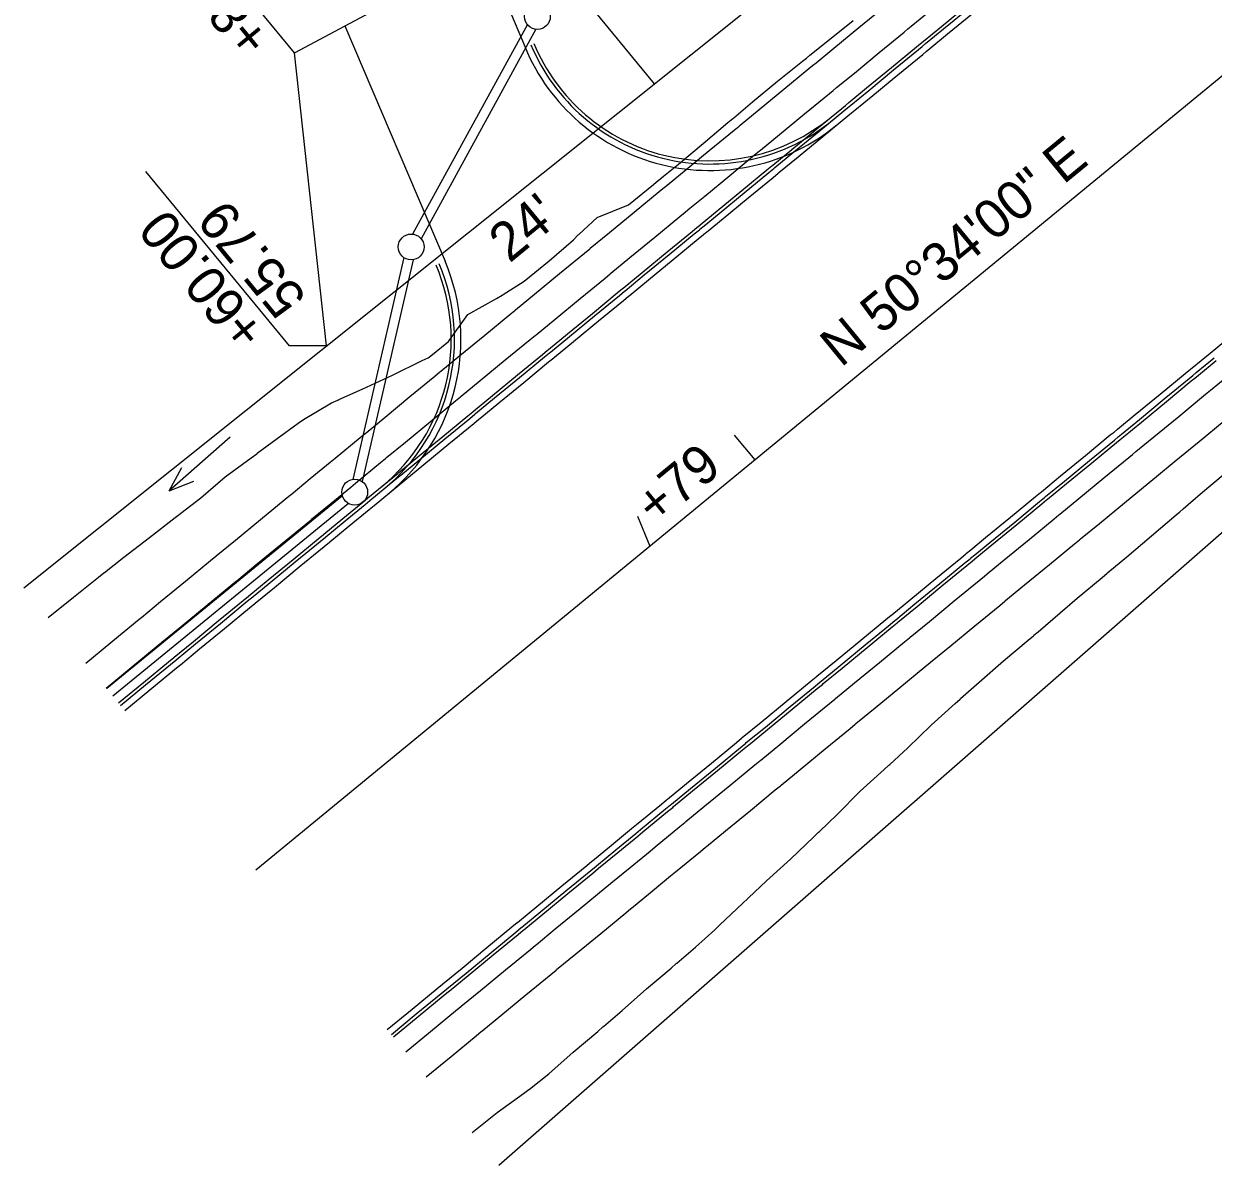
# Model space of a CAD drawing. Extents: x 1147550 to 1149124, y 2017436 to 2018779.
# Drawn here: x 1147550.1 to 1147734.3, y 2017436.4 to 2017613.3 of the extents above; entities that cross this region are included whole.
import ezdxf

# ---------------------------------------------------------------- set-up
doc = ezdxf.new("R2010")
doc.units = 0
for name, color, linetype in [('S_EDGE_CONCRETE', 7, 'Continuous'), ('S_ELECTRIC_UTILITIES', 7, 'Continuous'), ('S_HEADWALL', 7, 'Continuous'), ('S_MAILBOX', 7, 'Continuous'), ('S_RDW_PT_SYM', 7, 'Continuous'), ('S_SECONDARY_CTL', 7, 'Continuous'), ('S_TANK', 7, 'Continuous'), ('S_TELEPHONE_UTILITIES', 7, 'Continuous'), ('S_TELEPHONE_UTILITIES_ANNOT', 7, 'Continuous')]:
    doc.layers.add(name, color=color, linetype=linetype)

msp = doc.modelspace()

# ---------------------------------------------------------------- linework, layer by layer
at = {"layer": 'S_EDGE_CONCRETE'}
msp.add_line((1147586.06, 2017482.16), (1147825.51, 2017679.08), dxfattribs=at)
msp.add_lwpolyline([(1147660.13, 2017549.54), (1147663.3, 2017545.68)], dxfattribs=at)
at = {"layer": 'S_ELECTRIC_UTILITIES'}
for points in [[(1147592.01, 2017608.75), (1147569.78, 2017635.79)], [(1147596.97, 2017563.36), (1147591.24, 2017563.36), (1147569.01, 2017590.39)]]:
    msp.add_lwpolyline(points, dxfattribs=at)
at = {"layer": 'S_HEADWALL'}
for p, q in [((1147621.53, 2017624.53), (1147627.73, 2017609.62)), ((1147599.83, 2017612.94), (1147615.34, 2017576.47)), ((1147645.14, 2017536.95), (1147647.08, 2017532.34))]:
    msp.add_line(p, q, dxfattribs=at)
for centre, radius, start, end in [((1147656.35, 2017621.53), 31, 202.599, 309.4333), ((1147656.35, 2017621.53), 30, 202.599, 309.4333), ((1147656.35, 2017621.53), 29.5, 202.599, 309.4333), ((1147586.81, 2017564.34), 30, 309.4333, 23.0331), ((1147586.81, 2017564.34), 31, 309.4333, 23.0331), ((1147586.81, 2017564.34), 29.5, 309.4333, 23.0331)]:
    msp.add_arc(centre, radius, start, end, dxfattribs=at)
at = {"layer": 'S_MAILBOX'}
msp.add_line((1147627.98, 2017627.98), (1147647.75, 2017603.95), dxfattribs=at)
for points in [[(1147550.1, 2017525.89), (1147894.72, 2017801.4), (1147903.55, 2017831.14), (1148035.64, 2017933.4), (1148261.5, 2018084.85), (1148285.74, 2018084.65), (1148479.1, 2018223.18), (1148835.76, 2018573.62)], [(1147623.68, 2017436.42), (1147751.67, 2017548.43), (1147958.55, 2017704.02), (1148020.45, 2017753.36), (1148124.6, 2017828.73), (1148174.25, 2017853.51), (1148282.74, 2017941.53), (1148421.63, 2018031.39), (1148612.18, 2018197.22), (1148639.91, 2018214.06), (1148753.45, 2018306.48), (1148799.03, 2018350.69)], [(1147596.97, 2017563.36), (1147592.01, 2017608.75), (1147627.98, 2017627.98)]]:
    msp.add_lwpolyline(points, dxfattribs=at)
at = {"layer": 'S_SECONDARY_CTL'}
for points in [[(1147553.88, 2017521.3), (1147557.78, 2017524.42), (1147561.69, 2017527.55), (1147562.51, 2017528.21), (1147562.59, 2017528.27), (1147565.62, 2017530.64), (1147569.58, 2017533.69), (1147573.54, 2017536.75), (1147574.38, 2017537.39), (1147574.45, 2017537.45), (1147577.5, 2017539.8), (1147581.3, 2017543.06), (1147585.33, 2017546.03), (1147586.19, 2017546.65), (1147586.26, 2017546.71), (1147589.37, 2017548.99), (1147592.6, 2017551.36), (1147593.41, 2017551.95), (1147597.76, 2017554.52), (1147598.72, 2017554.95), (1147598.9, 2017555.03), (1147602.49, 2017556.65), (1147607.19, 2017558.8), (1147611.81, 2017561.07), (1147612.75, 2017561.52), (1147612.9, 2017561.59), (1147615.86, 2017564.01), (1147618.88, 2017568.2), (1147623.3, 2017570.71), (1147624.2, 2017571.22), (1147624.34, 2017571.3), (1147627.59, 2017573.36), (1147631.47, 2017576.51), (1147635.23, 2017579.81), (1147635.98, 2017580.54), (1147636.06, 2017580.62), (1147638.9, 2017583.22), (1147643.75, 2017585.19), (1147647.61, 2017588.37), (1147648.42, 2017589.03), (1147648.51, 2017589.1), (1147649.17, 2017589.63), (1147651.51, 2017591.51), (1147655.34, 2017594.72), (1147659.16, 2017597.95), (1147659.92, 2017598.59), (1147660.07, 2017598.71), (1147662.98, 2017601.17), (1147666.83, 2017604.36), (1147670.73, 2017607.49), (1147671.31, 2017607.95), (1147671.85, 2017608.38), (1147674.64, 2017610.61), (1147678.54, 2017613.74)], [(1147619.52, 2017441.48), (1147623.43, 2017444.6), (1147627.49, 2017447.54), (1147628.34, 2017448.16), (1147628.42, 2017448.21), (1147631.44, 2017450.6), (1147635.19, 2017453.92), (1147638.99, 2017457.16), (1147639.8, 2017457.85), (1147639.87, 2017457.9), (1147642.8, 2017460.41), (1147646.54, 2017463.73), (1147650.35, 2017466.97), (1147651.15, 2017467.65), (1147651.22, 2017467.71), (1147654.15, 2017470.22), (1147657.11, 2017472.91), (1147657.85, 2017473.59), (1147661.49, 2017477.04), (1147662.22, 2017477.73), (1147662.36, 2017477.86), (1147665.14, 2017480.47), (1147668.83, 2017483.85), (1147672.46, 2017487.31), (1147673.2, 2017488.01), (1147673.32, 2017488.12), (1147676.08, 2017490.78), (1147679.62, 2017494.35), (1147683.33, 2017497.71), (1147684.09, 2017498.39), (1147684.21, 2017498.5), (1147687.01, 2017501.11), (1147690.61, 2017504.6), (1147694.33, 2017507.94), (1147695.11, 2017508.64), (1147695.19, 2017508.72), (1147698.06, 2017511.28), (1147701.84, 2017514.56), (1147705.66, 2017517.79), (1147706.46, 2017518.46), (1147706.54, 2017518.53), (1147707.19, 2017519.08), (1147709.47, 2017521.03), (1147713.26, 2017524.28), (1147717.1, 2017527.49), (1147717.87, 2017528.13), (1147718.01, 2017528.25), (1147720.93, 2017530.7), (1147724.75, 2017533.94), (1147728.56, 2017537.18), (1147729.12, 2017537.65), (1147729.64, 2017538.1), (1147732.37, 2017540.41), (1147736.17, 2017543.66)]]:
    msp.add_lwpolyline(points, dxfattribs=at)
at = {"layer": 'S_TANK'}
for p, q in [((1147582.05, 2017549.22), (1147572.61, 2017540.92)), ((1147572.61, 2017540.92), (1147574.57, 2017544.51)), ((1147572.61, 2017540.92), (1147576.42, 2017542.41))]:
    msp.add_line(p, q, dxfattribs=at)
at = {"layer": 'S_TELEPHONE_UTILITIES'}
for points in [[(1147559.7, 2017514.22), (1147563.57, 2017517.39), (1147567.43, 2017520.57), (1147568.24, 2017521.24), (1147568.32, 2017521.3), (1147571.29, 2017523.74), (1147575.15, 2017526.92), (1147579.01, 2017530.09), (1147579.83, 2017530.77), (1147579.9, 2017530.82), (1147582.88, 2017533.27), (1147586.74, 2017536.45), (1147590.6, 2017539.62), (1147591.42, 2017540.29), (1147591.49, 2017540.35), (1147594.46, 2017542.8), (1147597.55, 2017545.34), (1147598.32, 2017545.97), (1147602.18, 2017549.15), (1147602.96, 2017549.79), (1147603.11, 2017549.91), (1147606.05, 2017552.33), (1147609.91, 2017555.5), (1147613.77, 2017558.68), (1147614.56, 2017559.32), (1147614.68, 2017559.43), (1147617.63, 2017561.85), (1147621.49, 2017565.03), (1147625.36, 2017568.21), (1147626.14, 2017568.85), (1147626.27, 2017568.96), (1147629.22, 2017571.38), (1147633.08, 2017574.56), (1147636.94, 2017577.73), (1147637.75, 2017578.4), (1147637.83, 2017578.47), (1147640.8, 2017580.91), (1147644.66, 2017584.08), (1147648.53, 2017587.26), (1147649.33, 2017587.92), (1147649.42, 2017587.99), (1147650.07, 2017588.53), (1147652.39, 2017590.44), (1147656.25, 2017593.61), (1147660.11, 2017596.79), (1147660.88, 2017597.42), (1147661.03, 2017597.54), (1147663.97, 2017599.96), (1147667.84, 2017603.14), (1147671.7, 2017606.32), (1147672.26, 2017606.78), (1147672.8, 2017607.22), (1147675.56, 2017609.49), (1147679.42, 2017612.67), (1147683.28, 2017615.84)], [(1147562.88, 2017510.35), (1147566.74, 2017513.53), (1147570.6, 2017516.71), (1147571.42, 2017517.38), (1147571.49, 2017517.44), (1147574.47, 2017519.88), (1147578.33, 2017523.06), (1147582.19, 2017526.23), (1147583.01, 2017526.9), (1147583.08, 2017526.96), (1147586.05, 2017529.41), (1147589.91, 2017532.58), (1147593.78, 2017535.76), (1147594.59, 2017536.43), (1147594.66, 2017536.49), (1147597.64, 2017538.94), (1147600.73, 2017541.48), (1147601.5, 2017542.11), (1147605.36, 2017545.29), (1147606.14, 2017545.93), (1147606.28, 2017546.05), (1147609.22, 2017548.46), (1147613.08, 2017551.64), (1147616.95, 2017554.82), (1147617.73, 2017555.46), (1147617.86, 2017555.57), (1147620.81, 2017557.99), (1147624.67, 2017561.17), (1147628.53, 2017564.34), (1147629.32, 2017564.99), (1147629.44, 2017565.09), (1147632.39, 2017567.52), (1147636.26, 2017570.7), (1147640.12, 2017573.87), (1147640.92, 2017574.53), (1147641.01, 2017574.6), (1147643.98, 2017577.05), (1147647.84, 2017580.22), (1147651.7, 2017583.4), (1147652.51, 2017584.06), (1147652.59, 2017584.13), (1147653.25, 2017584.67), (1147655.56, 2017586.57), (1147659.43, 2017589.75), (1147663.29, 2017592.93), (1147664.06, 2017593.56), (1147664.21, 2017593.68), (1147667.15, 2017596.1), (1147671.01, 2017599.28), (1147674.87, 2017602.45), (1147675.44, 2017602.92), (1147675.97, 2017603.36), (1147678.74, 2017605.63), (1147682.6, 2017608.81), (1147686.46, 2017611.98), (1147687.02, 2017612.45), (1147687.56, 2017612.88), (1147690.32, 2017615.16)], [(1147564.79, 2017508.04), (1147568.65, 2017511.21), (1147572.51, 2017514.39), (1147573.33, 2017515.06), (1147573.4, 2017515.12), (1147576.37, 2017517.56), (1147580.23, 2017520.74), (1147584.1, 2017523.92), (1147584.91, 2017524.59), (1147584.98, 2017524.64), (1147587.96, 2017527.09), (1147591.82, 2017530.27), (1147595.68, 2017533.44), (1147596.5, 2017534.12), (1147596.57, 2017534.17), (1147599.54, 2017536.62), (1147602.63, 2017539.16), (1147603.4, 2017539.8), (1147607.27, 2017542.97), (1147608.04, 2017543.61), (1147608.19, 2017543.73), (1147611.13, 2017546.15), (1147614.99, 2017549.32), (1147618.85, 2017552.5), (1147619.64, 2017553.15), (1147619.76, 2017553.25), (1147622.71, 2017555.67), (1147626.58, 2017558.85), (1147630.44, 2017562.03), (1147631.22, 2017562.67), (1147631.35, 2017562.78), (1147634.3, 2017565.2), (1147638.16, 2017568.38), (1147642.02, 2017571.55), (1147642.83, 2017572.22), (1147642.91, 2017572.29), (1147645.88, 2017574.73), (1147649.75, 2017577.91), (1147653.61, 2017581.08), (1147654.41, 2017581.74), (1147654.5, 2017581.81), (1147655.15, 2017582.35), (1147657.47, 2017584.26), (1147661.33, 2017587.43), (1147665.19, 2017590.61), (1147665.97, 2017591.25), (1147666.11, 2017591.36), (1147669.06, 2017593.79), (1147672.92, 2017596.96), (1147676.78, 2017600.14), (1147677.34, 2017600.6), (1147677.88, 2017601.04), (1147680.64, 2017603.31), (1147684.5, 2017606.49), (1147688.36, 2017609.66), (1147688.93, 2017610.13), (1147689.46, 2017610.57), (1147692.23, 2017612.84), (1147696.09, 2017616.02)], [(1147565.1, 2017507.65), (1147568.97, 2017510.83), (1147572.83, 2017514), (1147573.64, 2017514.67), (1147573.72, 2017514.73), (1147576.69, 2017517.18), (1147580.55, 2017520.35), (1147584.41, 2017523.53), (1147585.23, 2017524.2), (1147585.3, 2017524.26), (1147588.27, 2017526.71), (1147592.14, 2017529.88), (1147596, 2017533.06), (1147596.82, 2017533.73), (1147596.88, 2017533.79), (1147599.86, 2017536.23), (1147602.95, 2017538.77), (1147603.72, 2017539.41), (1147607.58, 2017542.58), (1147608.36, 2017543.22), (1147608.51, 2017543.34), (1147611.45, 2017545.76), (1147615.31, 2017548.94), (1147619.17, 2017552.11), (1147619.96, 2017552.76), (1147620.08, 2017552.86), (1147623.03, 2017555.29), (1147626.89, 2017558.46), (1147630.75, 2017561.64), (1147631.54, 2017562.29), (1147631.67, 2017562.39), (1147634.62, 2017564.82), (1147638.48, 2017567.99), (1147642.34, 2017571.17), (1147643.15, 2017571.83), (1147643.23, 2017571.9), (1147646.2, 2017574.34), (1147650.06, 2017577.52), (1147653.93, 2017580.7), (1147654.73, 2017581.36), (1147654.82, 2017581.43), (1147655.47, 2017581.97), (1147657.79, 2017583.87), (1147661.65, 2017587.05), (1147665.51, 2017590.22), (1147666.28, 2017590.86), (1147666.43, 2017590.98), (1147669.37, 2017593.4), (1147673.23, 2017596.58), (1147677.1, 2017599.75), (1147677.66, 2017600.22), (1147678.2, 2017600.66), (1147680.96, 2017602.93), (1147684.82, 2017606.1), (1147688.68, 2017609.28), (1147689.25, 2017609.74), (1147689.78, 2017610.18), (1147692.54, 2017612.45), (1147696.41, 2017615.63)], [(1147565.74, 2017506.88), (1147569.6, 2017510.05), (1147573.46, 2017513.23), (1147574.28, 2017513.9), (1147574.35, 2017513.96), (1147577.32, 2017516.41), (1147581.19, 2017519.58), (1147585.05, 2017522.76), (1147585.87, 2017523.43), (1147585.93, 2017523.49), (1147588.91, 2017525.93), (1147592.77, 2017529.11), (1147596.63, 2017532.28), (1147597.45, 2017532.96), (1147597.52, 2017533.01), (1147600.5, 2017535.46), (1147603.58, 2017538), (1147604.36, 2017538.64), (1147608.22, 2017541.81), (1147608.99, 2017542.45), (1147609.14, 2017542.57), (1147612.08, 2017544.99), (1147615.94, 2017548.16), (1147619.8, 2017551.34), (1147620.59, 2017551.99), (1147620.72, 2017552.09), (1147623.67, 2017554.52), (1147627.53, 2017557.69), (1147631.39, 2017560.87), (1147632.18, 2017561.51), (1147632.3, 2017561.62), (1147635.25, 2017564.04), (1147639.11, 2017567.22), (1147642.98, 2017570.4), (1147643.78, 2017571.06), (1147643.87, 2017571.13), (1147646.84, 2017573.57), (1147650.7, 2017576.75), (1147654.56, 2017579.92), (1147655.37, 2017580.59), (1147655.45, 2017580.66), (1147656.11, 2017581.19), (1147658.42, 2017583.1), (1147662.28, 2017586.28), (1147666.15, 2017589.45), (1147666.92, 2017590.09), (1147667.06, 2017590.21), (1147670.01, 2017592.63), (1147673.87, 2017595.8), (1147677.73, 2017598.98), (1147678.3, 2017599.44), (1147678.83, 2017599.88), (1147681.59, 2017602.15), (1147685.46, 2017605.33), (1147689.32, 2017608.51), (1147689.88, 2017608.97), (1147690.42, 2017609.41), (1147693.18, 2017611.68), (1147697.04, 2017614.86)], [(1147606.39, 2017457.45), (1147610.25, 2017460.62), (1147614.11, 2017463.8), (1147614.93, 2017464.47), (1147615, 2017464.53), (1147617.98, 2017466.97), (1147621.84, 2017470.15), (1147625.7, 2017473.33), (1147626.52, 2017474), (1147626.59, 2017474.05), (1147629.56, 2017476.5), (1147633.42, 2017479.68), (1147637.28, 2017482.85), (1147638.1, 2017483.53), (1147638.17, 2017483.58), (1147641.15, 2017486.03), (1147644.24, 2017488.57), (1147645.01, 2017489.21), (1147648.87, 2017492.38), (1147649.65, 2017493.02), (1147649.79, 2017493.14), (1147652.73, 2017495.56), (1147656.59, 2017498.73), (1147660.46, 2017501.91), (1147661.24, 2017502.56), (1147661.37, 2017502.66), (1147664.32, 2017505.08), (1147668.18, 2017508.26), (1147672.04, 2017511.44), (1147672.83, 2017512.08), (1147672.95, 2017512.19), (1147675.9, 2017514.61), (1147679.76, 2017517.79), (1147683.63, 2017520.96), (1147684.43, 2017521.63), (1147684.52, 2017521.7), (1147687.49, 2017524.14), (1147691.35, 2017527.32), (1147695.21, 2017530.49), (1147696.02, 2017531.15), (1147696.1, 2017531.22), (1147696.76, 2017531.76), (1147699.07, 2017533.67), (1147702.94, 2017536.84), (1147706.8, 2017540.02), (1147707.57, 2017540.66), (1147707.72, 2017540.77), (1147710.66, 2017543.2), (1147714.52, 2017546.37), (1147718.38, 2017549.55), (1147718.95, 2017550.01), (1147719.48, 2017550.45), (1147722.25, 2017552.72), (1147726.11, 2017555.9), (1147729.97, 2017559.08), (1147730.53, 2017559.54), (1147731.07, 2017559.98), (1147733.83, 2017562.25), (1147737.69, 2017565.43)], [(1147607.03, 2017456.67), (1147610.89, 2017459.85), (1147614.75, 2017463.03), (1147615.56, 2017463.7), (1147615.64, 2017463.76), (1147618.61, 2017466.2), (1147622.47, 2017469.38), (1147626.33, 2017472.55), (1147627.15, 2017473.23), (1147627.22, 2017473.28), (1147630.2, 2017475.73), (1147634.06, 2017478.91), (1147637.92, 2017482.08), (1147638.74, 2017482.75), (1147638.81, 2017482.81), (1147641.78, 2017485.26), (1147644.87, 2017487.8), (1147645.64, 2017488.43), (1147649.51, 2017491.61), (1147650.28, 2017492.25), (1147650.43, 2017492.37), (1147653.37, 2017494.78), (1147657.23, 2017497.96), (1147661.09, 2017501.14), (1147661.88, 2017501.78), (1147662, 2017501.89), (1147664.95, 2017504.31), (1147668.81, 2017507.49), (1147672.68, 2017510.66), (1147673.46, 2017511.31), (1147673.59, 2017511.41), (1147676.54, 2017513.84), (1147680.4, 2017517.02), (1147684.26, 2017520.19), (1147685.07, 2017520.85), (1147685.15, 2017520.93), (1147688.12, 2017523.37), (1147691.99, 2017526.54), (1147695.85, 2017529.72), (1147696.65, 2017530.38), (1147696.74, 2017530.45), (1147697.39, 2017530.99), (1147699.71, 2017532.9), (1147703.57, 2017536.07), (1147707.43, 2017539.25), (1147708.21, 2017539.88), (1147708.35, 2017540), (1147711.29, 2017542.42), (1147715.16, 2017545.6), (1147719.02, 2017548.77), (1147719.58, 2017549.24), (1147720.12, 2017549.68), (1147722.88, 2017551.95), (1147726.74, 2017555.13), (1147730.6, 2017558.3), (1147731.17, 2017558.77), (1147731.7, 2017559.21), (1147734.47, 2017561.48)], [(1147607.34, 2017456.29), (1147611.2, 2017459.46), (1147615.07, 2017462.64), (1147615.88, 2017463.31), (1147615.96, 2017463.37), (1147618.93, 2017465.82), (1147622.79, 2017468.99), (1147626.65, 2017472.17), (1147627.47, 2017472.84), (1147627.54, 2017472.9), (1147630.51, 2017475.34), (1147634.38, 2017478.52), (1147638.24, 2017481.69), (1147639.05, 2017482.37), (1147639.12, 2017482.42), (1147642.1, 2017484.87), (1147645.19, 2017487.41), (1147645.96, 2017488.05), (1147649.82, 2017491.22), (1147650.6, 2017491.86), (1147650.75, 2017491.98), (1147653.69, 2017494.4), (1147657.55, 2017497.57), (1147661.41, 2017500.75), (1147662.2, 2017501.4), (1147662.32, 2017501.5), (1147665.27, 2017503.93), (1147669.13, 2017507.1), (1147672.99, 2017510.28), (1147673.78, 2017510.92), (1147673.91, 2017511.03), (1147676.86, 2017513.45), (1147680.72, 2017516.63), (1147684.58, 2017519.81), (1147685.39, 2017520.47), (1147685.47, 2017520.54), (1147688.44, 2017522.98), (1147692.3, 2017526.16), (1147696.17, 2017529.33), (1147696.97, 2017530), (1147697.06, 2017530.07), (1147697.71, 2017530.6), (1147700.03, 2017532.51), (1147703.89, 2017535.69), (1147707.75, 2017538.86), (1147708.52, 2017539.5), (1147708.67, 2017539.62), (1147711.61, 2017542.04), (1147715.47, 2017545.21), (1147719.34, 2017548.39), (1147719.9, 2017548.85), (1147720.44, 2017549.29), (1147723.2, 2017551.56), (1147727.06, 2017554.74), (1147730.92, 2017557.92), (1147731.49, 2017558.38), (1147732.02, 2017558.82), (1147734.78, 2017561.09)], [(1147609.25, 2017453.97), (1147613.11, 2017457.15), (1147616.97, 2017460.32), (1147617.79, 2017460.99), (1147617.86, 2017461.05), (1147620.83, 2017463.5), (1147624.7, 2017466.67), (1147628.56, 2017469.85), (1147629.38, 2017470.52), (1147629.44, 2017470.58), (1147632.42, 2017473.03), (1147636.28, 2017476.2), (1147640.14, 2017479.38), (1147640.96, 2017480.05), (1147641.03, 2017480.11), (1147644.01, 2017482.55), (1147647.09, 2017485.09), (1147647.87, 2017485.73), (1147651.73, 2017488.91), (1147652.5, 2017489.54), (1147652.65, 2017489.66), (1147655.59, 2017492.08), (1147659.45, 2017495.26), (1147663.31, 2017498.43), (1147664.1, 2017499.08), (1147664.23, 2017499.18), (1147667.18, 2017501.61), (1147671.04, 2017504.79), (1147674.9, 2017507.96), (1147675.69, 2017508.61), (1147675.81, 2017508.71), (1147678.76, 2017511.14), (1147682.62, 2017514.31), (1147686.49, 2017517.49), (1147687.29, 2017518.15), (1147687.38, 2017518.22), (1147690.35, 2017520.66), (1147694.21, 2017523.84), (1147698.07, 2017527.02), (1147698.88, 2017527.68), (1147698.96, 2017527.75), (1147699.62, 2017528.29), (1147701.93, 2017530.19), (1147705.79, 2017533.37), (1147709.66, 2017536.54), (1147710.43, 2017537.18), (1147710.57, 2017537.3), (1147713.52, 2017539.72), (1147717.38, 2017542.9), (1147721.24, 2017546.07), (1147721.81, 2017546.54), (1147722.34, 2017546.98), (1147725.1, 2017549.25), (1147728.97, 2017552.42), (1147732.83, 2017555.6), (1147733.39, 2017556.06), (1147733.92, 2017556.5), (1147736.69, 2017558.78)], [(1147612.42, 2017450.11), (1147616.29, 2017453.28), (1147620.15, 2017456.46), (1147620.96, 2017457.13), (1147621.04, 2017457.19), (1147624.01, 2017459.64), (1147627.87, 2017462.81), (1147631.73, 2017465.99), (1147632.55, 2017466.66), (1147632.62, 2017466.72), (1147635.6, 2017469.16), (1147639.46, 2017472.34), (1147643.32, 2017475.52), (1147644.14, 2017476.19), (1147644.21, 2017476.24), (1147647.18, 2017478.69), (1147650.27, 2017481.23), (1147651.04, 2017481.87), (1147654.9, 2017485.04), (1147655.68, 2017485.68), (1147655.83, 2017485.8), (1147658.77, 2017488.22), (1147662.63, 2017491.4), (1147666.49, 2017494.57), (1147667.28, 2017495.22), (1147667.4, 2017495.32), (1147670.35, 2017497.75), (1147674.21, 2017500.92), (1147678.08, 2017504.1), (1147678.86, 2017504.75), (1147678.99, 2017504.85), (1147681.94, 2017507.27), (1147685.8, 2017510.45), (1147689.66, 2017513.63), (1147690.47, 2017514.29), (1147690.55, 2017514.36), (1147693.52, 2017516.8), (1147697.38, 2017519.98), (1147701.25, 2017523.15), (1147702.05, 2017523.82), (1147702.14, 2017523.89), (1147702.79, 2017524.42), (1147705.11, 2017526.33), (1147708.97, 2017529.51), (1147712.83, 2017532.68), (1147713.6, 2017533.32), (1147713.75, 2017533.44), (1147716.69, 2017535.86), (1147720.56, 2017539.03), (1147724.42, 2017542.21), (1147724.98, 2017542.68), (1147725.52, 2017543.11), (1147728.28, 2017545.39), (1147732.14, 2017548.56), (1147736, 2017551.74)]]:
    msp.add_lwpolyline(points, dxfattribs=at)
at = {"layer": 'S_TELEPHONE_UTILITIES_ANNOT'}
for p, q in [((1147628.1, 2017613.12), (1147610.33, 2017580.67)), ((1147628.1, 2017613.12), (1147610.33, 2017580.67)), ((1147629.42, 2017612.4), (1147611.65, 2017579.95)), ((1147629.42, 2017612.4), (1147611.65, 2017579.95)), ((1147608.95, 2017577.04), (1147601.05, 2017542.68)), ((1147608.95, 2017577.04), (1147601.05, 2017542.68)), ((1147610.42, 2017576.71), (1147602.51, 2017542.34)), ((1147610.42, 2017576.71), (1147602.51, 2017542.34)), ((1147599.45, 2017540.11), (1147562.95, 2017510.27)), ((1147599.45, 2017540.11), (1147562.95, 2017510.27)), ((1147600.4, 2017538.95), (1147563.9, 2017509.11)), ((1147600.4, 2017538.95), (1147563.9, 2017509.11))]:
    msp.add_line(p, q, dxfattribs=at)
for centre in [(1147629.65, 2017614.38), (1147610.1, 2017578.68), (1147601.36, 2017540.7)]:
    msp.add_circle(centre, 2, dxfattribs=at)

# ---------------------------------------------------------------- texts
at = {"layer": 'S_ELECTRIC_UTILITIES'}
for s, p in [('+85.00', (1147588.7, 2017611.21)), ('55.79', (1147594.1, 2017570.9)), ('+60.00', (1147587.92, 2017565.81))]:
    msp.add_text(s, height=6, rotation=129.4333, dxfattribs=at).set_placement(p)
at = {"layer": 'S_HEADWALL'}
for s, p in [("24'", (1147625.33, 2017576.09)), ('+79', (1147647.95, 2017535.39))]:
    msp.add_text(s, height=6, rotation=39.4333, dxfattribs=at).set_placement(p)
at = {"layer": 'S_RDW_PT_SYM'}
msp.add_text('N 50%%d34\'00" E', height=6, rotation=39.4333, dxfattribs=at).set_placement((1147676.66, 2017559.91))

doc.saveas('drawing.dxf')
